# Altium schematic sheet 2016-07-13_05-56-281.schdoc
size 267 x 118 mm; SheetNumber: 1; SheetTotal: 1
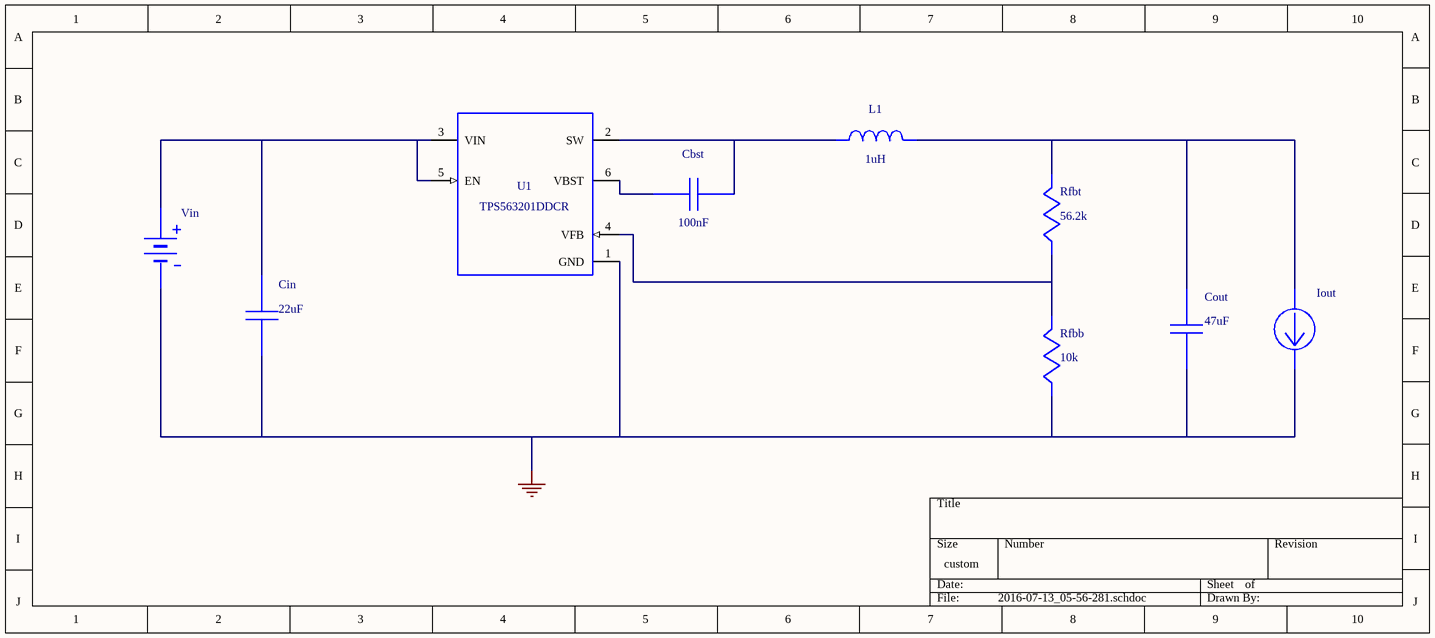
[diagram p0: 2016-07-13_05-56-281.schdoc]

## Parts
Cbst  value 100nF  (hidden comment: 08053C104KAT2A)
Cin  value 22uF  (hidden comment: GRM32ER61E226KE15L)
Cout  value 47uF  (hidden comment: C3216X5R1E476M160AC)
Iout  WB_CURRENT_LOAD  (value not drawn)
L1  value 1uH  (hidden comment: XFL6012-102MEB)
Rfbb  value 10k  (hidden comment: CRCW040210K0FKED)
Rfbt  value 56.2k  (hidden comment: CRCW040256K2FKED)
U1  TPS563201DDCR
Vin  WB_BATTERY  (value not drawn)

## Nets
0: Cin.2 Cout.2 Iout.2(-) Rfbb.2 U1.1(GND) Vin.2(-)
NetCbst_1: Cbst.1 L1.1 U1.2(SW)
NetCbst_2: Cbst.2 U1.6(VBST)
NetCin_1: Cin.1 U1.3(VIN) U1.5(EN) Vin.1(+)
NetCout_1: Cout.1 Iout.1(+) L1.2 Rfbt.1
NetRfbb_1: Rfbb.1 Rfbt.2 U1.4(VFB)

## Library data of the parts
Cbst = 08053C104KAT2A: Manufacturer Name: AVX
Cin = GRM32ER61E226KE15L: GRM32ER61E226KE1; Manufacturer Name: MuRata
Cout = C3216X5R1E476M160AC: C3216X5R1E476M16; Manufacturer Name: TDK
L1 = XFL6012-102MEB: Unknown; Manufacturer Name: Coilcraft
Rfbb = CRCW040210K0FKED: Manufacturer Name: Vishay-Dale
Rfbt = CRCW040256K2FKED: Manufacturer Name: Vishay-Dale
U1 = TPS563201DDCR: Manufacturer Name: Texas Instruments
